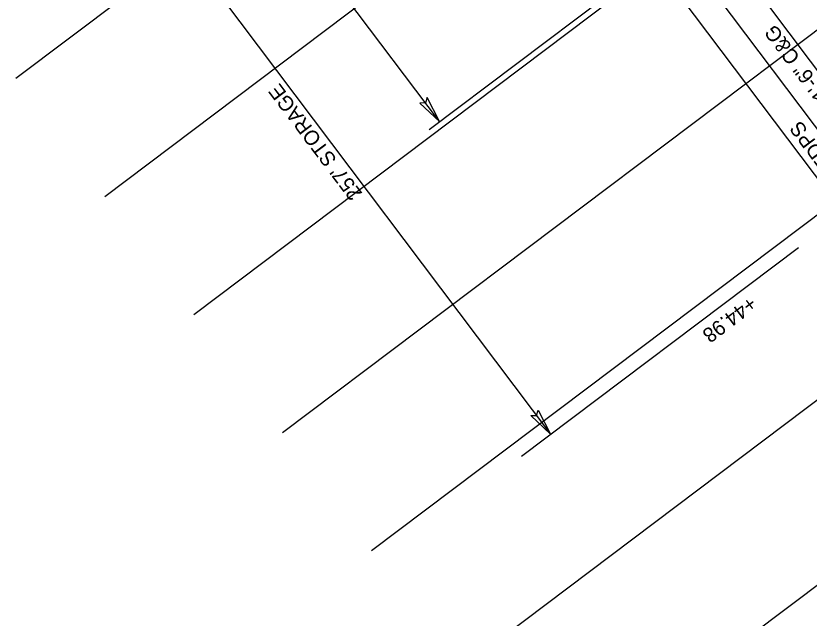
# Model space of a CAD drawing. Extents: x 1262309 to 1264352, y 775189 to 777755.
# Drawn here: x 1262694.6 to 1262963, y 776879.5 to 777083.2 of the extents above; entities that cross this region are included whole.
import ezdxf

# ---------------------------------------------------------------- set-up
doc = ezdxf.new("R2010")
doc.units = 0
for name, color, linetype in [('Prop Dimension', 7, 'Continuous'), ('Prop Dimension Text', 7, 'Continuous'), ('Prop EOT', 7, 'Continuous'), ('Prop Lane Lines', 7, 'Continuous'), ('Prop Paved Shoulder', 7, 'Continuous'), ('Scratch_Level_3', 7, 'Continuous')]:
    doc.layers.add(name, color=color, linetype=linetype)

msp = doc.modelspace()

# ---------------------------------------------------------------- linework, layer by layer
at = {"layer": 'Prop Dimension Text'}
for p, q in [((1262837.95, 777047.44), (1262747.7, 777167.25)), ((1262875.57, 776941.71), (1262720.9, 777147.06)), ((1262834.45, 777044.8), (1262910.33, 777101.95)), ((1262865.72, 776934.33), (1262959.38, 777004.87))]:
    msp.add_line(p, q, dxfattribs=at)
for points in [[(1262831.3, 777053.69), (1262837.95, 777047.44), (1262833.79, 777055.63), (1262833.2, 777053.75)], [(1262871.38, 776949.85), (1262875.55, 776941.73), (1262868.83, 776948), (1262870.8, 776948.04)]]:
    msp.add_lwpolyline(points, close=True, dxfattribs=at)
at = {"layer": 'Prop EOT'}
msp.add_line((1263058.9, 776921.33), (1262918.32, 777107.97), dxfattribs=at)
at = {"layer": 'Prop Lane Lines'}
msp.add_lwpolyline([(1263120.31, 776859.74), (1262792.29, 777295.24)], dxfattribs=at)
at = {"layer": 'Prop Paved Shoulder'}
msp.add_line((1263065.65, 776895.74), (1262896.15, 777120.79), dxfattribs=at)
at = {"layer": 'Scratch_Level_3'}
for p, q in [((1262694.59, 777062.1), (1263189.7, 777435.02)), ((1262724.68, 777022.16), (1263219.78, 777395.08)), ((1262754.76, 776982.22), (1263249.86, 777355.14)), ((1262784.84, 776942.29), (1263279.94, 777315.2)), ((1262814.92, 776902.35), (1263310.02, 777275.26)), ((1262845, 776862.41), (1263340.11, 777235.32)), ((1262875.09, 776822.47), (1263370.19, 777195.38))]:
    msp.add_line(p, q, dxfattribs=at)

# ---------------------------------------------------------------- texts
at = {"layer": 'Prop Dimension'}
msp.add_text('1\'-6" C&G', height=5, rotation=127.0213, dxfattribs=at).set_placement((1262969.3, 777056.98))
at = {"layer": 'Prop Dimension Text'}
for s, rotation, p in [("257' STORAGE", 126.9874, (1262812, 777023.18)), ("10' FDPS", 126.9874, (1262977.15, 777025.37)), ('+44.98', 216.9874, (1262942.94, 776988.69))]:
    msp.add_text(s, height=5, rotation=rotation, dxfattribs=at).set_placement(p)

doc.saveas('drawing.dxf')
